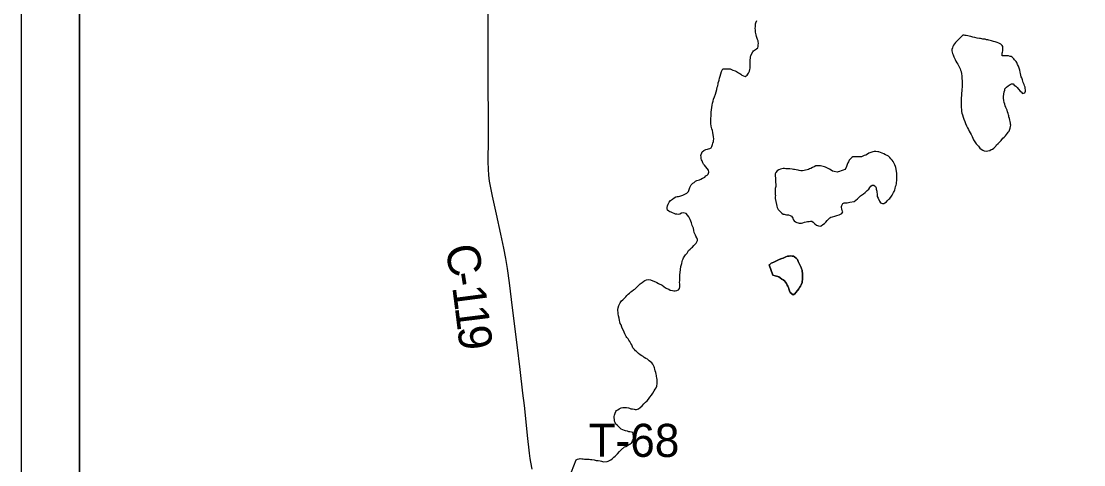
# Model space of a CAD drawing. Extents: x -17 to 88, y -5 to 22.
# Drawn here: x -17.26 to -15.435, y 15.263 to 16.025 of the extents above; entities that cross this region are included whole.
import ezdxf

# ---------------------------------------------------------------- set-up
doc = ezdxf.new("R2010")
doc.units = 0
for name, color, linetype in [('Default', 7, 'Continuous'), ('GM_X_County_Road', 7, 'Continuous'), ('GM_X_County_Road_Text', 7, 'Continuous'), ('GM_X_Minor_Lake', 7, 'Continuous'), ('GM_X_Minor_River', 7, 'Continuous'), ('GM_X_Township_Road_Text', 7, 'Continuous'), ('SH_Data', 7, 'Continuous')]:
    doc.layers.add(name, color=color, linetype=linetype)

msp = doc.modelspace()

# ---------------------------------------------------------------- linework, layer by layer
at = {"layer": 'Default'}
msp.add_lwpolyline([(-17.1602, 20.9), (-10.3602, 20.9), (-10.3602, 14.1), (-17.1602, 14.1)], close=True, dxfattribs=at)
at = {"layer": 'GM_X_County_Road'}
msp.add_lwpolyline([(-16.3824, 15.2559), (-16.3847, 15.2678), (-16.3858, 15.2738), (-16.3871, 15.283), (-16.3901, 15.3133), (-16.392, 15.3312), (-16.3958, 15.3652), (-16.3983, 15.3862), (-16.4032, 15.4269), (-16.4082, 15.4689), (-16.4159, 15.5324), (-16.4212, 15.5756), (-16.4247, 15.6002), (-16.4276, 15.6174), (-16.431, 15.6351), (-16.4362, 15.6594), (-16.4437, 15.6934), (-16.4506, 15.7244), (-16.4536, 15.7389), (-16.4554, 15.7499), (-16.4566, 15.7604), (-16.4574, 15.7709), (-16.4577, 15.7833), (-16.4576, 15.823), (-16.4576, 15.8553), (-16.4578, 15.9193), (-16.4578, 15.9616), (-16.4578, 16.0417)], dxfattribs=at)
at = {"layer": 'GM_X_Minor_Lake'}
for points in [[(-15.6425, 16.001), (-15.655, 15.9881), (-15.6565, 15.9862), (-15.6584, 15.9835), (-15.6596, 15.9812), (-15.6603, 15.9793), (-15.6615, 15.9763), (-15.6615, 15.974), (-15.6607, 15.9714), (-15.66, 15.9695), (-15.6592, 15.9672), (-15.6577, 15.9638), (-15.6565, 15.9615), (-15.6558, 15.9592), (-15.6543, 15.9562), (-15.6524, 15.9531), (-15.6508, 15.9509), (-15.6493, 15.9478), (-15.6482, 15.9452), (-15.647, 15.9429), (-15.6463, 15.9406), (-15.6455, 15.9383), (-15.6448, 15.9345), (-15.644, 15.9311), (-15.644, 15.9269), (-15.6436, 15.922), (-15.6436, 15.9182), (-15.6436, 15.9148), (-15.6436, 15.9114), (-15.644, 15.9083), (-15.644, 15.9053), (-15.6448, 15.9015), (-15.6448, 15.8973), (-15.6451, 15.8931), (-15.6455, 15.8863), (-15.6455, 15.8802), (-15.6444, 15.87), (-15.644, 15.8669), (-15.6428, 15.8639), (-15.6417, 15.8601), (-15.6406, 15.8567), (-15.639, 15.8525), (-15.6379, 15.8491), (-15.636, 15.8453), (-15.6341, 15.8419), (-15.6326, 15.8388), (-15.6315, 15.8362), (-15.6299, 15.8331), (-15.628, 15.8301), (-15.6265, 15.8267), (-15.6254, 15.824), (-15.6239, 15.8214), (-15.6216, 15.8176), (-15.6193, 15.8142), (-15.6155, 15.8104), (-15.6132, 15.8069), (-15.6106, 15.8054), (-15.6079, 15.8035), (-15.6056, 15.8024), (-15.6022, 15.8016), (-15.5996, 15.802), (-15.5962, 15.8031), (-15.5935, 15.8043), (-15.5912, 15.8054), (-15.5893, 15.8069), (-15.5874, 15.8088), (-15.5855, 15.8104), (-15.5844, 15.8123), (-15.5817, 15.8149), (-15.5787, 15.818), (-15.5764, 15.8202), (-15.5734, 15.824), (-15.5715, 15.8259), (-15.5692, 15.8282), (-15.5673, 15.8301), (-15.5654, 15.8324), (-15.5643, 15.8343), (-15.5628, 15.8362), (-15.5609, 15.8411), (-15.5605, 15.8442), (-15.5601, 15.8461)], [(-15.5601, 15.8461), (-15.5605, 15.848), (-15.5605, 15.8499), (-15.5609, 15.8529), (-15.5616, 15.8548), (-15.562, 15.8575), (-15.5632, 15.8605), (-15.5635, 15.8624), (-15.5639, 15.8643), (-15.5647, 15.8666), (-15.5654, 15.8692), (-15.5662, 15.8719), (-15.5673, 15.8742), (-15.5685, 15.8768), (-15.5696, 15.8795), (-15.5704, 15.8825), (-15.5711, 15.8852), (-15.5719, 15.8886), (-15.5723, 15.8928), (-15.5723, 15.8958), (-15.5719, 15.8996), (-15.5711, 15.9034), (-15.5704, 15.9064), (-15.57, 15.9087), (-15.5674, 15.9118), (-15.5647, 15.914), (-15.5613, 15.9159), (-15.559, 15.9175), (-15.5556, 15.9171), (-15.5541, 15.9152), (-15.5514, 15.9133), (-15.5491, 15.911), (-15.5469, 15.9083), (-15.5438, 15.9049), (-15.5419, 15.9034), (-15.5397, 15.9007), (-15.5359, 15.9019), (-15.5347, 15.9049), (-15.5347, 15.9072), (-15.5351, 15.9095), (-15.5355, 15.9118), (-15.5362, 15.9137), (-15.537, 15.9163), (-15.5385, 15.9197), (-15.5393, 15.922), (-15.54, 15.9243), (-15.5408, 15.9277), (-15.5419, 15.9296), (-15.5427, 15.9323), (-15.5431, 15.9349), (-15.5438, 15.9376), (-15.5446, 15.9406), (-15.5457, 15.9444), (-15.5465, 15.9478), (-15.5484, 15.9505), (-15.5495, 15.9539), (-15.5507, 15.9558), (-15.5533, 15.9585), (-15.5548, 15.9604), (-15.5575, 15.963), (-15.5594, 15.9642), (-15.5613, 15.9645), (-15.564, 15.9653), (-15.5662, 15.9653), (-15.5693, 15.9653), (-15.5715, 15.9653), (-15.575, 15.9653), (-15.575, 15.968), (-15.5746, 15.9699), (-15.5742, 15.9718), (-15.5738, 15.9737), (-15.5734, 15.9759), (-15.5734, 15.9778), (-15.5734, 15.9812), (-15.575, 15.9831), (-15.5772, 15.9854), (-15.5807, 15.9873), (-15.5833, 15.9881), (-15.5867, 15.9892), (-15.5894, 15.99), (-15.5913, 15.9904), (-15.5932, 15.9911), (-15.5955, 15.9915), (-15.5977, 15.9923), (-15.5996, 15.9926), (-15.6019, 15.993), (-15.6042, 15.9938), (-15.6061, 15.9942), (-15.608, 15.9942), (-15.6099, 15.9945), (-15.6118, 15.9949), (-15.6137, 15.9953), (-15.6178, 15.9957), (-15.6216, 15.9968), (-15.6254, 15.9976), (-15.6288, 15.9983), (-15.6364, 16.0002), (-15.6383, 16.0002), (-15.6402, 16.0006), (-15.6414, 16.001), (-15.6425, 16.001)], [(-15.7604, 15.7325), (-15.7593, 15.7355), (-15.7585, 15.7378), (-15.7578, 15.7412), (-15.757, 15.7431), (-15.7566, 15.7454), (-15.7563, 15.7477), (-15.7559, 15.7511), (-15.7559, 15.7534), (-15.7559, 15.7564), (-15.7559, 15.7583), (-15.7559, 15.7602), (-15.7559, 15.7633), (-15.757, 15.7708), (-15.7574, 15.7735), (-15.7578, 15.7754), (-15.7593, 15.7784), (-15.7601, 15.7803), (-15.762, 15.7838), (-15.7639, 15.786), (-15.7661, 15.7887), (-15.7677, 15.7906), (-15.7703, 15.7929), (-15.7722, 15.794), (-15.7752, 15.7955), (-15.7779, 15.797), (-15.7809, 15.7982), (-15.784, 15.7993), (-15.7866, 15.8005), (-15.7885, 15.8008), (-15.7916, 15.8012), (-15.7946, 15.8012), (-15.7969, 15.8005), (-15.7988, 15.8001), (-15.8007, 15.7993), (-15.8037, 15.7982), (-15.8064, 15.7963), (-15.809, 15.7948), (-15.8117, 15.794), (-15.8139, 15.7929), (-15.8162, 15.7921), (-15.8223, 15.7917), (-15.8257, 15.7921), (-15.8287, 15.7921), (-15.8314, 15.7917), (-15.8333, 15.7906), (-15.8356, 15.7883), (-15.8375, 15.786), (-15.839, 15.7834), (-15.8397, 15.7815), (-15.8409, 15.7788), (-15.842, 15.7754), (-15.8432, 15.7727), (-15.8454, 15.7701), (-15.8481, 15.7689), (-15.8515, 15.7678), (-15.8542, 15.767), (-15.8564, 15.7663), (-15.8583, 15.7659), (-15.8633, 15.7667), (-15.8663, 15.7674), (-15.8686, 15.7693), (-15.8716, 15.7705), (-15.8739, 15.772), (-15.8762, 15.7731), (-15.8781, 15.7743), (-15.8803, 15.775), (-15.8822, 15.7754), (-15.8845, 15.7761), (-15.8872, 15.7765), (-15.8902, 15.7765), (-15.8921, 15.7765), (-15.8948, 15.7765), (-15.8978, 15.775), (-15.9005, 15.7735), (-15.9035, 15.772), (-15.9058, 15.7712), (-15.9077, 15.7701), (-15.9096, 15.7697), (-15.9126, 15.7689), (-15.9152, 15.7685), (-15.9179, 15.7682), (-15.9209, 15.7682), (-15.9236, 15.7685), (-15.9255, 15.7689), (-15.9285, 15.7697), (-15.9316, 15.7701), (-15.9335, 15.7704), (-15.9357, 15.7708), (-15.9395, 15.7712), (-15.9422, 15.7712), (-15.9448, 15.7716), (-15.9467, 15.7716), (-15.949, 15.772), (-15.9513, 15.772), (-15.9532, 15.7716), (-15.9558, 15.7708), (-15.9585, 15.7697), (-15.9612, 15.7678), (-15.9634, 15.7651), (-15.9646, 15.7625)], [(-15.9646, 15.7625), (-15.9638, 15.7412), (-15.9646, 15.7378), (-15.9649, 15.7351), (-15.9649, 15.7328), (-15.9646, 15.7294)], [(-15.9646, 15.7294), (-15.9646, 15.7272), (-15.9642, 15.7253), (-15.9646, 15.723), (-15.9646, 15.7207), (-15.9627, 15.7104), (-15.9619, 15.7074), (-15.9615, 15.7047), (-15.9596, 15.7017), (-15.957, 15.6987), (-15.9551, 15.6972), (-15.9535, 15.6953), (-15.9513, 15.6937), (-15.9494, 15.6934), (-15.9475, 15.693), (-15.9452, 15.6926), (-15.9418, 15.6922), (-15.9391, 15.6915), (-15.9369, 15.6899), (-15.9346, 15.6865), (-15.9338, 15.6846), (-15.9319, 15.682), (-15.9296, 15.6801), (-15.9274, 15.6793), (-15.9255, 15.6785), (-15.9236, 15.6782), (-15.9194, 15.6782), (-15.9171, 15.6786), (-15.9145, 15.6797), (-15.9114, 15.6805), (-15.9092, 15.6808), (-15.9065, 15.6812), (-15.9042, 15.6816), (-15.9019, 15.6816), (-15.8997, 15.6797), (-15.8966, 15.677), (-15.894, 15.6748), (-15.8906, 15.6732), (-15.8875, 15.6729), (-15.8856, 15.6736), (-15.883, 15.6755), (-15.8803, 15.6774), (-15.878, 15.6797), (-15.8754, 15.6824), (-15.8735, 15.6843), (-15.8708, 15.6873), (-15.8689, 15.6881), (-15.8663, 15.6892), (-15.8625, 15.6903), (-15.8587, 15.6915), (-15.8549, 15.6926), (-15.8526, 15.6938), (-15.85, 15.6949), (-15.8488, 15.6975), (-15.8496, 15.6998), (-15.8503, 15.7029), (-15.8507, 15.7048), (-15.8507, 15.7067), (-15.8503, 15.7086), (-15.8488, 15.7116), (-15.8462, 15.7127), (-15.8431, 15.7131), (-15.8412, 15.7131), (-15.8386, 15.7135), (-15.8363, 15.7139), (-15.8291, 15.7154), (-15.8264, 15.7173), (-15.8234, 15.7196), (-15.8204, 15.7226), (-15.8181, 15.7249), (-15.8162, 15.7264), (-15.8128, 15.7283), (-15.8101, 15.731), (-15.8067, 15.7344), (-15.8041, 15.7367), (-15.8022, 15.7393), (-15.8007, 15.7416), (-15.7984, 15.7431), (-15.7953, 15.7431), (-15.7927, 15.7412), (-15.7915, 15.7386), (-15.7912, 15.7363), (-15.7904, 15.7329), (-15.7904, 15.731), (-15.7896, 15.7283), (-15.7893, 15.7241), (-15.7877, 15.7211), (-15.7855, 15.7158), (-15.7836, 15.7131), (-15.7805, 15.7116), (-15.7783, 15.7116), (-15.7764, 15.7127), (-15.7737, 15.7146), (-15.7718, 15.7169), (-15.7695, 15.7192), (-15.7676, 15.7207), (-15.765, 15.7245), (-15.7638, 15.7264), (-15.7627, 15.7283), (-15.7616, 15.7306), (-15.7604, 15.7325)], [(-15.9178, 15.5829), (-15.9178, 15.5855), (-15.9178, 15.5886), (-15.9179, 15.592), (-15.9182, 15.595), (-15.9186, 15.5973), (-15.9194, 15.5996), (-15.9201, 15.6018), (-15.9217, 15.6056), (-15.9228, 15.6079), (-15.9239, 15.6102), (-15.9251, 15.6125), (-15.9266, 15.6159), (-15.9289, 15.6182), (-15.9315, 15.6201), (-15.9334, 15.6212), (-15.9357, 15.6216), (-15.9391, 15.622), (-15.941, 15.6216), (-15.9437, 15.6212), (-15.9467, 15.6201), (-15.949, 15.6193), (-15.9512, 15.6182), (-15.9535, 15.6174), (-15.9577, 15.6159), (-15.9672, 15.6113), (-15.9698, 15.6102), (-15.9717, 15.6091), (-15.974, 15.6072), (-15.9749, 15.6064)], [(-15.9749, 15.6064), (-15.974, 15.6072), (-15.9717, 15.6091), (-15.9698, 15.6102), (-15.9672, 15.6113), (-15.9577, 15.6159), (-15.9535, 15.6174), (-15.9512, 15.6182), (-15.949, 15.6193), (-15.9467, 15.6201), (-15.9437, 15.6212), (-15.941, 15.6216), (-15.9391, 15.622), (-15.9357, 15.6216), (-15.9334, 15.6212), (-15.9315, 15.6201), (-15.9289, 15.6182), (-15.9266, 15.6159), (-15.9251, 15.6125), (-15.9239, 15.6102), (-15.9228, 15.6079), (-15.9217, 15.6056), (-15.9201, 15.6018), (-15.9194, 15.5996), (-15.9186, 15.5973), (-15.9182, 15.595), (-15.9179, 15.592), (-15.9178, 15.5886), (-15.9178, 15.5855), (-15.9178, 15.5829), (-15.9178, 15.5806), (-15.9182, 15.5787), (-15.9186, 15.5764), (-15.9201, 15.5722), (-15.9213, 15.5699), (-15.9228, 15.5677), (-15.9243, 15.5654), (-15.9262, 15.5627), (-15.9292, 15.5589), (-15.9311, 15.557), (-15.9338, 15.5551), (-15.9391, 15.5589), (-15.9402, 15.562), (-15.9414, 15.5654), (-15.9421, 15.5677), (-15.9429, 15.5699), (-15.944, 15.5718), (-15.9455, 15.5745), (-15.9471, 15.5768), (-15.949, 15.5791), (-15.9512, 15.581), (-15.9531, 15.5821), (-15.9562, 15.5844), (-15.9585, 15.5859), (-15.9603, 15.5863), (-15.9626, 15.587), (-15.9649, 15.5878), (-15.9687, 15.5889), (-15.9749, 15.6064)], [(-15.9749, 15.6064), (-15.9687, 15.5889), (-15.9649, 15.5878), (-15.9626, 15.587), (-15.9603, 15.5863), (-15.9585, 15.5859), (-15.9562, 15.5844), (-15.9531, 15.5821), (-15.9512, 15.581), (-15.949, 15.5791), (-15.9471, 15.5768), (-15.9455, 15.5745), (-15.944, 15.5718), (-15.9429, 15.5699), (-15.9421, 15.5677), (-15.9414, 15.5654), (-15.9402, 15.562), (-15.9391, 15.5589), (-15.9338, 15.5551), (-15.9311, 15.557), (-15.9292, 15.5589), (-15.9262, 15.5627), (-15.9243, 15.5654), (-15.9228, 15.5677), (-15.9213, 15.5699), (-15.9201, 15.5722), (-15.9186, 15.5764), (-15.9182, 15.5787), (-15.9178, 15.5806), (-15.9178, 15.5829)]]:
    msp.add_lwpolyline(points, dxfattribs=at)
at = {"layer": 'GM_X_Minor_River'}
for points in [[(-16.0708, 15.827), (-16.0716, 15.83), (-16.072, 15.8338), (-16.0727, 15.8369), (-16.0735, 15.8399), (-16.0742, 15.8426), (-16.075, 15.8449), (-16.0754, 15.8494), (-16.0754, 15.8524), (-16.0754, 15.8559), (-16.0754, 15.8585), (-16.075, 15.8616), (-16.075, 15.8646), (-16.0746, 15.8688), (-16.0743, 15.8726), (-16.0739, 15.8768), (-16.0731, 15.8805), (-16.0724, 15.884), (-16.0716, 15.8874), (-16.0705, 15.8912), (-16.0693, 15.895), (-16.0674, 15.8995), (-16.0663, 15.9033), (-16.0652, 15.9075), (-16.0644, 15.9117), (-16.0636, 15.914), (-16.0629, 15.9174), (-16.0625, 15.9193), (-16.0614, 15.9219), (-16.061, 15.9238), (-16.0602, 15.9273), (-16.0591, 15.9303), (-16.0583, 15.9345), (-16.0568, 15.9383), (-16.0561, 15.9405), (-16.0545, 15.9428), (-16.0481, 15.9428), (-16.0462, 15.9428), (-16.0443, 15.9428), (-16.0424, 15.9428), (-16.0401, 15.9421), (-16.0375, 15.9409), (-16.0337, 15.9394), (-16.031, 15.9383), (-16.028, 15.9364), (-16.0257, 15.9352), (-16.0238, 15.9341), (-16.0219, 15.9322), (-16.0193, 15.9311), (-16.0162, 15.9299), (-16.0132, 15.9322), (-16.0105, 15.9356), (-16.009, 15.939), (-16.0083, 15.9417), (-16.0079, 15.944), (-16.0079, 15.9463), (-16.0079, 15.9489), (-16.0079, 15.9512), (-16.0079, 15.9535), (-16.0075, 15.9565), (-16.0075, 15.9588), (-16.0071, 15.9614), (-16.0071, 15.9633), (-16.0064, 15.966), (-16.0033, 15.9721), (-16.0018, 15.974), (-15.9988, 15.9763), (-15.9969, 15.9774), (-15.9946, 15.9793), (-15.9942, 15.9816), (-15.9939, 15.9835), (-15.9935, 15.9869), (-15.9939, 15.9892), (-15.9942, 15.9914), (-15.995, 15.9933), (-15.9961, 15.9968), (-15.9969, 15.9987), (-15.9977, 16.0013), (-15.998, 16.0036), (-15.9984, 16.0059), (-15.9988, 16.0093), (-15.9992, 16.0127), (-15.9988, 16.0154), (-15.9988, 16.0184), (-15.9984, 16.0203), (-15.998, 16.0222), (-15.9965, 16.026)], [(-16.119, 15.6235), (-16.1163, 15.6265), (-16.1136, 15.6314), (-16.111, 15.6337), (-16.1087, 15.6356), (-16.1068, 15.6371), (-16.1045, 15.6398), (-16.1023, 15.6421), (-16.1004, 15.644), (-16.0996, 15.6459), (-16.0985, 15.6482), (-16.0985, 15.65), (-16.0996, 15.6527), (-16.1011, 15.6557), (-16.1019, 15.6576), (-16.103, 15.6599), (-16.1042, 15.6622), (-16.1046, 15.6652), (-16.1053, 15.6694), (-16.1065, 15.6717), (-16.1072, 15.674), (-16.108, 15.6762), (-16.1087, 15.6789), (-16.1099, 15.6816), (-16.1106, 15.6846), (-16.1121, 15.6869), (-16.1133, 15.6892), (-16.1156, 15.6918), (-16.1178, 15.6945), (-16.1228, 15.696), (-16.1258, 15.6952), (-16.1288, 15.6933), (-16.1311, 15.693), (-16.1338, 15.6933), (-16.1361, 15.6937), (-16.1383, 15.6945), (-16.141, 15.6956), (-16.1436, 15.6967), (-16.1459, 15.6975), (-16.1478, 15.6986), (-16.1497, 15.7002), (-16.1505, 15.7024), (-16.1505, 15.7047), (-16.1497, 15.7081), (-16.1486, 15.7108), (-16.1467, 15.7142), (-16.1444, 15.7169), (-16.1414, 15.7192), (-16.1383, 15.7214), (-16.1353, 15.723), (-16.133, 15.7237), (-16.1311, 15.7241), (-16.1285, 15.7245), (-16.1254, 15.7256), (-16.1235, 15.7264), (-16.1213, 15.7275), (-16.119, 15.7286), (-16.1167, 15.7298), (-16.1137, 15.7324), (-16.1114, 15.7393), (-16.1103, 15.7416), (-16.1091, 15.7438), (-16.1065, 15.7465), (-16.1038, 15.748), (-16.1015, 15.7499), (-16.0993, 15.7511), (-16.097, 15.7518), (-16.0947, 15.7522), (-16.0924, 15.7537), (-16.0898, 15.7552), (-16.0879, 15.756), (-16.0856, 15.7568), (-16.0837, 15.7594), (-16.0818, 15.7606), (-16.0799, 15.7621), (-16.0788, 15.7655), (-16.0795, 15.7689), (-16.0818, 15.7719), (-16.0837, 15.7746), (-16.0864, 15.7776), (-16.0879, 15.7795), (-16.089, 15.7814), (-16.0905, 15.7849), (-16.0913, 15.7868), (-16.0917, 15.789), (-16.0921, 15.7917), (-16.0924, 15.794), (-16.0902, 15.8004), (-16.0875, 15.8027), (-16.0841, 15.8046), (-16.0811, 15.8054), (-16.0792, 15.8057), (-16.0773, 15.8065), (-16.075, 15.8076), (-16.0739, 15.8095), (-16.0727, 15.8133), (-16.072, 15.8152), (-16.0708, 15.8183), (-16.0708, 15.8202), (-16.0704, 15.8224), (-16.0708, 15.827)], [(-16.1713, 15.4271), (-16.172, 15.4294), (-16.1728, 15.4313), (-16.1739, 15.4336), (-16.1751, 15.4359), (-16.177, 15.4381), (-16.1789, 15.44), (-16.1811, 15.4419), (-16.1842, 15.4446), (-16.1868, 15.4457), (-16.1899, 15.4476), (-16.1918, 15.4492), (-16.194, 15.4503), (-16.1967, 15.4522), (-16.1997, 15.4545), (-16.2028, 15.4575), (-16.2047, 15.459), (-16.2066, 15.4609), (-16.2092, 15.464), (-16.21, 15.4659), (-16.2111, 15.4689), (-16.2126, 15.4716), (-16.2145, 15.4746), (-16.216, 15.4769), (-16.2176, 15.4795), (-16.2195, 15.4818), (-16.2206, 15.4837), (-16.2217, 15.486), (-16.2233, 15.4883), (-16.2244, 15.4909), (-16.2282, 15.4993), (-16.2297, 15.5035), (-16.2309, 15.5057), (-16.2316, 15.5084), (-16.2324, 15.511), (-16.2331, 15.5148), (-16.2339, 15.519), (-16.2343, 15.5224), (-16.2347, 15.5251), (-16.235, 15.5278), (-16.235, 15.53), (-16.2347, 15.5327), (-16.2335, 15.5365), (-16.2312, 15.541), (-16.2286, 15.5448), (-16.2267, 15.5464), (-16.2237, 15.5494), (-16.2214, 15.5513), (-16.2195, 15.5536), (-16.2172, 15.5559), (-16.2149, 15.5581), (-16.213, 15.56), (-16.2111, 15.5612), (-16.2081, 15.5638), (-16.2058, 15.565), (-16.2028, 15.5676), (-16.2001, 15.5703), (-16.1967, 15.5737), (-16.1933, 15.5764), (-16.1907, 15.5783), (-16.1888, 15.5798), (-16.1857, 15.5809), (-16.1823, 15.5813), (-16.1793, 15.5809), (-16.1724, 15.5779), (-16.1702, 15.5771), (-16.1683, 15.5764), (-16.1652, 15.5745), (-16.163, 15.5733), (-16.1611, 15.5726), (-16.1592, 15.5714), (-16.1561, 15.5692), (-16.1531, 15.5673), (-16.1512, 15.5661), (-16.1478, 15.5646), (-16.1451, 15.5631), (-16.1413, 15.5623), (-16.139, 15.5619), (-16.1364, 15.5619), (-16.1337, 15.5623), (-16.1311, 15.5638), (-16.1292, 15.5661), (-16.1288, 15.5688), (-16.1288, 15.5718), (-16.1288, 15.5737), (-16.1292, 15.5764), (-16.1288, 15.5794), (-16.1288, 15.5813), (-16.1288, 15.5832), (-16.1288, 15.5859), (-16.1284, 15.5893), (-16.1281, 15.5935), (-16.1277, 15.5984), (-16.1269, 15.6037), (-16.1254, 15.609), (-16.1246, 15.6125), (-16.1243, 15.6147), (-16.1231, 15.6166), (-16.1224, 15.6185), (-16.1212, 15.6204), (-16.119, 15.6235)], [(-16.3145, 15.2511), (-16.3067, 15.2718), (-16.3044, 15.2729), (-16.3017, 15.2733), (-16.2998, 15.2737), (-16.2968, 15.2733), (-16.2949, 15.2733), (-16.2926, 15.2729), (-16.2903, 15.2729), (-16.2869, 15.2726), (-16.2847, 15.2726), (-16.282, 15.2722), (-16.2801, 15.2722), (-16.2759, 15.2714), (-16.2721, 15.2707), (-16.2687, 15.2703), (-16.2657, 15.2699), (-16.2634, 15.2695), (-16.26, 15.2684), (-16.2535, 15.2688), (-16.2516, 15.2695), (-16.2494, 15.2707), (-16.2471, 15.2718), (-16.2441, 15.2741), (-16.2418, 15.276), (-16.2399, 15.2779), (-16.2376, 15.2805), (-16.2357, 15.2821), (-16.2323, 15.2859), (-16.2296, 15.2889), (-16.2236, 15.2938), (-16.2213, 15.2946), (-16.2186, 15.2965), (-16.2167, 15.2976), (-16.2145, 15.2984), (-16.2114, 15.3007), (-16.2099, 15.3041), (-16.2088, 15.306), (-16.208, 15.3094), (-16.208, 15.3121), (-16.2088, 15.3166), (-16.2095, 15.3185), (-16.2114, 15.3193), (-16.2145, 15.3197), (-16.2164, 15.32), (-16.2187, 15.3208), (-16.2217, 15.3216), (-16.2236, 15.3223), (-16.2266, 15.3231), (-16.2293, 15.3246), (-16.2312, 15.3261), (-16.2365, 15.331), (-16.2384, 15.3329), (-16.2399, 15.336), (-16.2407, 15.3383), (-16.241, 15.3409), (-16.2414, 15.3436), (-16.2414, 15.3459), (-16.241, 15.3485), (-16.2399, 15.3516), (-16.2384, 15.3546), (-16.2376, 15.3565), (-16.2354, 15.3576), (-16.2327, 15.3595), (-16.2297, 15.3607), (-16.2266, 15.3614), (-16.224, 15.3614), (-16.2221, 15.3614), (-16.2202, 15.3614), (-16.2171, 15.361), (-16.2153, 15.3603), (-16.2126, 15.3595), (-16.2099, 15.3592), (-16.2073, 15.3584), (-16.2054, 15.358), (-16.2031, 15.358), (-16.1997, 15.3592), (-16.197, 15.3618), (-16.1932, 15.3645), (-16.1902, 15.3679), (-16.1876, 15.3705), (-16.1849, 15.3732), (-16.1826, 15.3759), (-16.18, 15.3793), (-16.1773, 15.3827), (-16.175, 15.3861), (-16.1728, 15.3899), (-16.1709, 15.3933), (-16.1693, 15.3956), (-16.1682, 15.3979), (-16.1675, 15.4028), (-16.1675, 15.4047), (-16.1678, 15.4066), (-16.1678, 15.4097), (-16.1682, 15.4127), (-16.1686, 15.4146), (-16.169, 15.4165), (-16.1694, 15.4188), (-16.1701, 15.4214), (-16.1709, 15.4245), (-16.1713, 15.4271)]]:
    msp.add_lwpolyline(points, dxfattribs=at)
at = {"layer": 'SH_Data'}
for p, q in [((-17.2602, 21), (-17.2602, 14)), ((-17.1602, 20.9), (-17.1602, 14.1))]:
    msp.add_line(p, q, dxfattribs=at)

# ---------------------------------------------------------------- texts
at = {"layer": 'GM_X_County_Road_Text'}
for s, rotation, p in [('C', 281.4213, (-16.5325, 15.6363)), ('-', 278.9509, (-16.5234, 15.5912)), ('1', 277.4052, (-16.5198, 15.5685)), ('1', 277.0327, (-16.5153, 15.5339)), ('9', 276.9591, (-16.511, 15.4992))]:
    msp.add_text(s, height=0.0568, rotation=rotation, dxfattribs=at).set_placement(p)
at = {"layer": 'GM_X_Township_Road_Text'}
msp.add_text('T-68', height=0.05682, rotation=359.8045, dxfattribs=at).set_placement((-16.2857, 15.2771))

doc.saveas('drawing.dxf')
